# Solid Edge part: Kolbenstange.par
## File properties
Username: bmolnar
Dokumentum tartalom típus: 0
Author: bmolnar
Last saved by: bmolnar
Revision: 82
Sűrűség: 0,000 kg/m^3
Pontosság: 0,990
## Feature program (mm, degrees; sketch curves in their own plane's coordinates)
base feature "unnamed BaseFeature 1"
sketch for "unnamed Protrusion 1" plane through (30, 0, 0) normal (1, 0, 0) x-axis (0, -1, 0)
  circle centre (0, 0) radius 31.5
extrude "unnamed Protrusion 1" add finite 18.25 along +normal
sketch for "Kihúzás_2" plane through (30, 0, 0) normal (1, 0, 0) x-axis (0, -1, 0)
  circle centre (0, 0) radius 31.5
extrude "Kihúzás_2" add finite 3.25 along -normal
sketch for "Furat_1" plane through (-25, 0, 0) normal (-1, 0, 0) x-axis (0, 0, -1)
  hole centre (0, 0) bore radius 4.188
hole "Furat_1" nominal diameter 10 finite  ThreadDepth = 17 mm
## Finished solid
Body 1: solid body, 16 faces, 22 edges, 8 vertices.
  Faces by surface: plane 9, cylinder 5, cone 1, torus 1
  Edges by curve: circle 12, line 6, ellipse 2, intersection 2
Bounding box of the edges (mm; curved faces can reach further): 73.250 x 63.000 x 63.000, from (-25, -31.5, -31.5) to (48.25, 31.5, 31.5).
Cylindrical faces by radius (mm): R4.18 x1, R4.188 x2, R8 x1, R31.5 x1
Conical faces (half-angle, radius in mm at the cone's reference point): 45 deg R4.18 x1
Toroidal faces (ring radius, tube radius in mm): R6.3 r1.7 x1
Planar faces by outward normal: +x 1, +z 1, -x 4, -z 1, oblique 2
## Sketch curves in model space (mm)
circle centre (30, 0, 0) radius 31.5
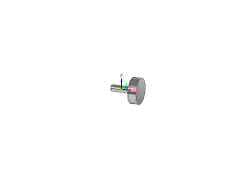
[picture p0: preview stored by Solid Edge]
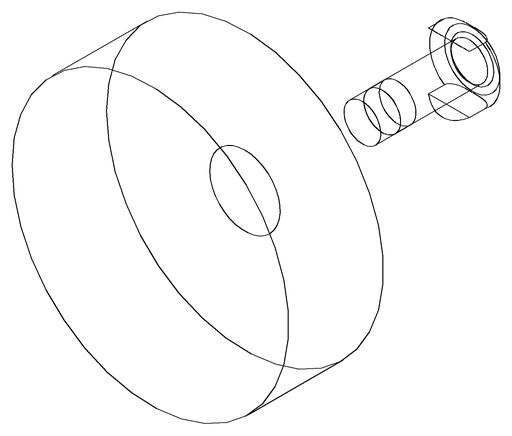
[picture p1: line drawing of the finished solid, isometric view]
